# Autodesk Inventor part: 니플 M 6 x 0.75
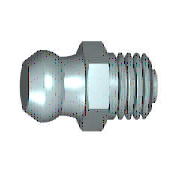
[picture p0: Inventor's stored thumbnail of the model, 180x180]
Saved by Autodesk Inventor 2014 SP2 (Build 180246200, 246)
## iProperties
IsCustomPart: 1
Created: 2012-02
Part Number: 니플 M 6 x 0.75
Material: 강철, 연강
Description: 윤활 니플, 원추 유형 A
Document SubType Name: Modeling
Standard: JIS B 1575
Designer: mduedu
Standards Organization: JIS
Language: ko-KR
Size Designation: MT 6 x 0.75
Categories: <MemberInstance><Categories><Category DisplayName="기타 부품" InternalName="5aa15e00-363f-49f2-933f-16f664388e3f" Mnemonic="OTHER"><Category DisplayName="그리스 부속품" I
Density: 1 g/cm^3
Appearance: 강철
Author: mduedu
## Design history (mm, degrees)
sketch "스케치1"
  geometry: L1 (-8.8, 0)-(-8.8, 2.4); L2 (-8.8, 2.4)-(-7.335, 3.202); L3 (-8.8, 0)-(4.7, 0); L4 (4.7, 0)-(4.7, 1.5); L5 (4.7, 1.5)-(4, 1.5); L6 (4, 1.5)-(4, 3); L7 (4, 3)-(0, 3); L8 (-11.5, 0)-(7.4, 0) reference; L9 (0, -1.733)-(0, 10.398) reference; L10 (-3, 3.5)-(0, 3.5); L11 (0, 3.5)-(0, 3); A1 r 3.3 centre (-6.535, 0) between (-4.789, 2.8) and (-7.335, 3.202); A2 r 6 centre (-6.053, 8.665) between (-4.789, 2.8) and (-3, 3.5)
  constraints: 18 end point, 5 perpendicular, 4 point on circle, 2 centre point, 2 parallel, 2 point on line, 1 collinear, 1 vertical
  dimensions: "d0" = 13.5 distance between parallel lines of L1 L4 (= GL); "d1" = 5.6 diameter of A1.start L3 (= KGB2); "d2" = 0.7 distance between parallel lines of L4 L6 (= PHH); "d3" = 3 diameter of L5 L3 (= 0.5 x NND); "d4" = 6 diameter of L7 L3 (= NND); "d5" = 6.6 dimension on A1 L3 (= KR); "d6" = 4.8 diameter of L1.end L3 (= KGB1); "d7" = 6 radius of A2 (= RBN); "d11" = 7 diameter of L10.start L3 (= SW); "d14" = 3 distance of L10.start L10.end (= KOH); "d15" = 4 distance between parallel lines of L6 L11 (= NLG); "d61" = 7.33505 distance from line of L9 L2.end (computed from KGB1, KR, PHH, GL, NLG, VERS); "d62" = 6.53505 distance from line of L9 A1.centre (computed from NLG, GL, PHH, KR, KGB1)
revolve "본체" sketch "스케치1" stored, may be unused: angle "d25" = 90 deg
sketch "스케치2"
  geometry: L1 (2.021, 3.5)-(4.041, 0); L2 (4.041, 0)-(2.021, -3.5); L3 (2.021, -3.5)-(-2.021, -3.5); L4 (-2.021, -3.5)-(-4.041, 0); L5 (-4.041, 0)-(-2.021, 3.5); L6 (-2.021, 3.5)-(2.021, 3.5); C1 r 3.5 at (0, 0) reference; 1 further point
  constraints: 12 end point, 1 coincident, 1 horizontal, 1 tangent, 11 other
extrude "머리" join sketch "스케치2" distance "d17" = 3 (= KOH); taper "d18" = 0 deg
sketch "스케치3"
  geometry: L1 (2.687, 4.041)-(3, 4.041); L2 (3, 4.041)-(3, 3.5); L3 (3, 3.5)-(2.687, 4.041); L4 (0.313, 4.041)-(0, 4.041); L5 (0, 4.041)-(0, 3.5); L6 (0, 3.5)-(0.313, 4.041); L7 (3.6, 0)-(-0.6, 0) reference; L8 (0, 4.041)-(0, 2.021) reference; L9 (0, 4.041)-(3, 4.041) reference; L10 (3, 3.031)-(3, 4.041) reference
  constraints: 12 end point, 4 collinear, 3 perpendicular, 1 horizontal
  dimensions: "d19" = 3.5 distance from line of L5.end L7 (= 0.5 x SW); "d20" = 3.5 distance from line of L2.end L7 (= 0.5 x SW); "d21" = 30 deg angle of L6 L5; "d22" = 30 deg angle of L2 L3
revolve "모따기1" sketch "스케치3" stored, may be unused: angle "d56" = 90 deg
body "Solid1"
fillet "모깎기1" dims "d8" = 0.2 (= RR)
feature "스레드1" dims "d9" = 3.53991 (= NLG - GAL), "d10" = 0
chamfer "모따기2" distance "d23" = 0.46009 (= -0.5 x GD1 + 0.5 x NND); stored, may be unused: angle "d24" = 45 deg, second distance "d59" = 0.46009 (= -0.5 x GD1 + 0.5 x NND)
other parameters: "NLG" = 4 [user parameter; used in 4 equation terms], "GL" = 13.5 [user parameter; used in 3 equation terms], "NND" = 6 [user parameter; used in 4 equation terms], "KGB1" = 4.8 [user parameter; used in 3 equation terms], "KGB2" = 5.6 [user parameter; used in 1 equation term], "VERS" = 0.8 [user parameter; used in 1 equation term], "KR" = 6.6 [user parameter; used in 3 equation terms], "RBN" = 6 [user parameter; used in 1 equation term], "SW" = 7 [user parameter; used in 3 equation terms], "KOH" = 3 [user parameter; used in 2 equation terms], "GAL" = 0.46009 (= 0.61345 x PTC) [user parameter; used in 1 equation term], "FAWI" = 45 deg [user parameter], "PHH" = 0.7 [user parameter; used in 3 equation terms], "GD1" = 5.07983 (= THREADDIA - 1.2269 x PTC) [user parameter; used in 2 equation terms], "RR" = 0.2 [user parameter; used in 1 equation term], "d12" = 0, "d13" = 0, "GUL" = 0.46009 (= 0.61345 x PTC) [user parameter], "TPU" = 13.33333 (computed from PTC) [user parameter], "DULO" = 1.5 [user parameter], "PTC" = 0.75 [user parameter; used in 4 equation terms], "GEL" = 4 [user parameter], "THREADDIA" = 6 [user parameter; used in 1 equation term], "TOA" = 30 deg [user parameter]
